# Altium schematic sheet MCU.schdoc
size 282 x 191 mm
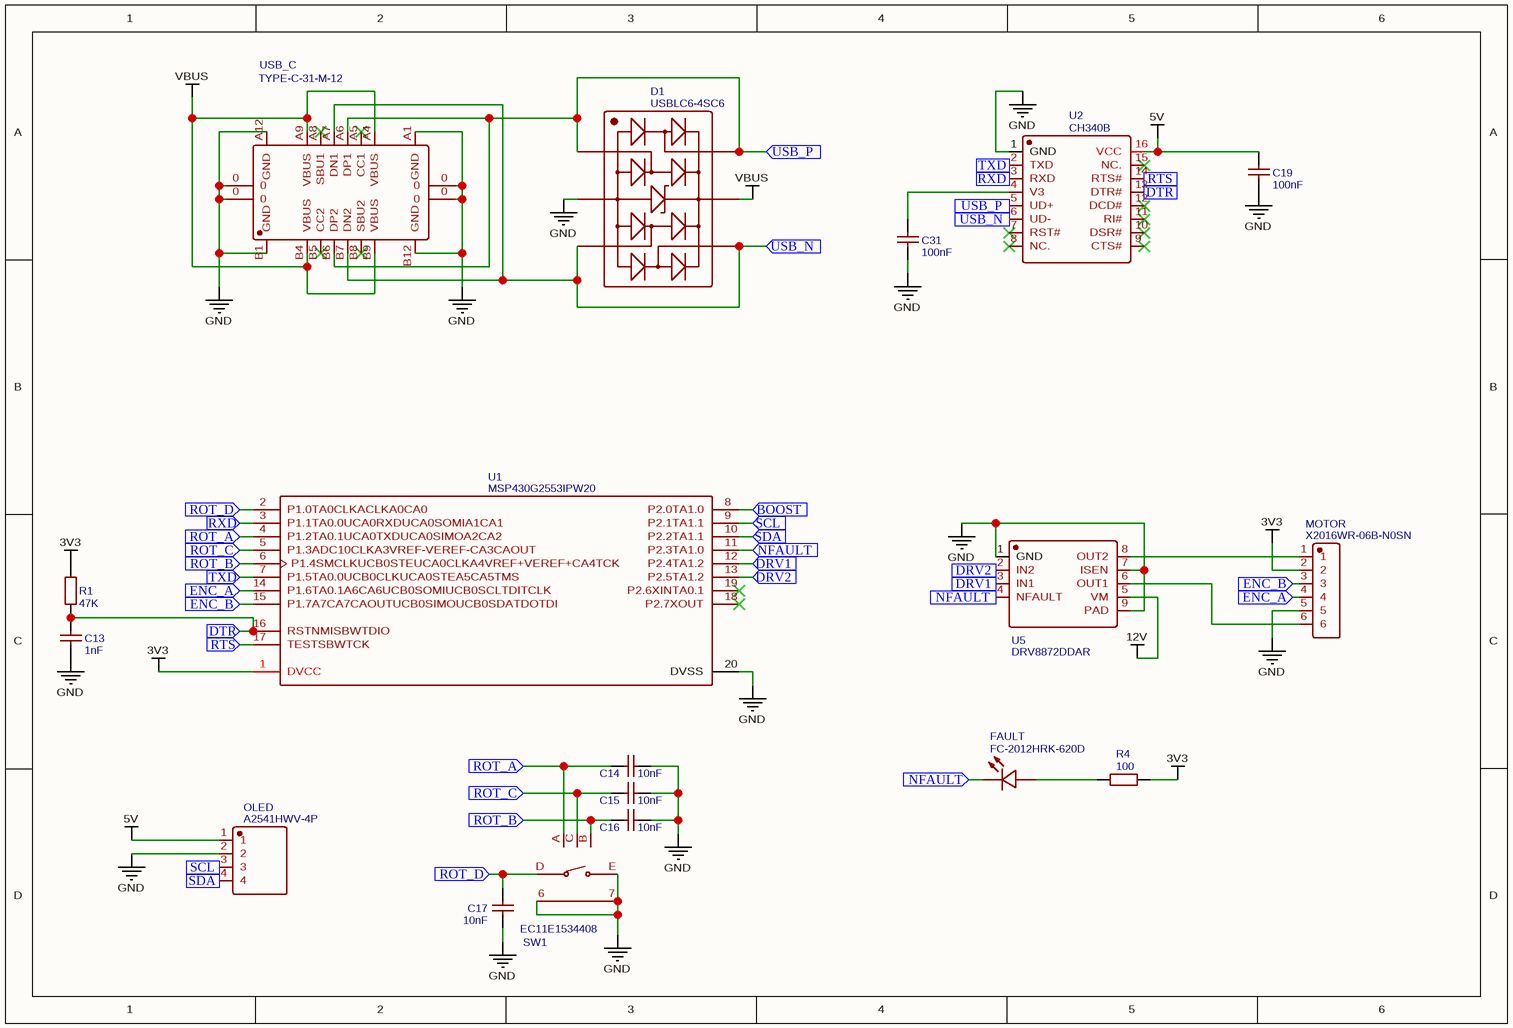
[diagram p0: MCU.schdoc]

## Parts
C13  1nF  [C0603]
C14  10nF  [C0603]
C15  10nF  [C0603]
C16  10nF  [C0603]
C17  10nF  [C0603]
C19  100nF  [C0805]
C31  100nF  [C0805]
D1  USBLC6-4SC6  [SOT-23-6_L2.9-W1.6-P0.95-LS2.8-BR]
FAULT  FC-2012HRK-620D  [LED0805-RD]
MOTOR  X2016WR-06B-N0SN  [CONN-TH_6P-P2.00_X2016WR-06B-N0SN]
OLED  A2541HWV-4P  [OLED12864]
R1  47K  [R0603]
R4  100  [R0603]
SW1  EC11E1534408  [SW-TH_EC11XXXXXXXX]
U1  MSP430G2553IPW20  [TSSOP-20_L6.5-W4.4-P0.65-LS6.4-BL]
U2  CH340B  [SOIC-16_L9.9-W3.9-P1.27-LS6.0-BL]
U5  DRV8872DDAR  [HSOP-8_L5.0-W4.0-P1.27-LS6.2-BL-EP]
USB_C  TYPE-C-31-M-12  [USB-C_SMD-TYPE-C-31-M-12]

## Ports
BOOST (in), DRV1 (in), DRV2 (in), DTR (in), ENC_A (in), ENC_B (in), NFAULT (in), ROT_A (in), ROT_B (in), ROT_C (in), ROT_D (in), RTS (in), RXD (in), SCL (in), SDA (in), TXD (in), USB_N (in), USB_P (in)

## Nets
3V3: MOTOR.2 R1.2 R4.2 U1.1(DVCC)
5V: C19.1 OLED.1 U2.16(VCC)
12V: U5.5(VM)
GND: C13.1 C14.2 C15.2 C16.2 C17.2 C19.2 C31.2 D1.2 MOTOR.5 OLED.2 SW1.6 SW1.7 SW1.E U1.20(DVSS) U2.1(GND) U5.1(GND) U5.7(ISEN) U5.9(PAD) USB_C.0 USB_C.A1(GND) USB_C.A12(GND) USB_C.B1(GND) USB_C.B12(GND)
VBUS: D1.5 USB_C.A4(VBUS) USB_C.A9(VBUS) USB_C.B4(VBUS) USB_C.B9(VBUS)
BOOST: U1.8(P2.0TA1.0) ; port BOOST
DRV1: U1.12(P2.4TA1.2) U5.3(IN1) ; port DRV1
DRV2: U1.13(P2.5TA1.2) U5.2(IN2) ; port DRV2
DTR: C13.2 R1.1 U1.16(RSTNMISBWTDIO) U2.13(DTR#) ; port DTR
ENC_A: MOTOR.4 U1.14(P1.6TA0.1A6CA6UCB0SOMIUCB0SCLTDITCLK) ; port ENC_A
ENC_B: MOTOR.3 U1.15(P1.7A7CA7CAOUTUCB0SIMOUCB0SDATDOTDI) ; port ENC_B
NFAULT: FAULT.1(-) U1.11(P2.3TA1.0) U5.4(NFAULT) ; port NFAULT
ROT_A: C14.1 SW1.A U1.4(P1.2TA0.1UCA0TXDUCA0SIMOA2CA2) ; port ROT_A
ROT_B: C16.1 SW1.B U1.6(P1.4SMCLKUCB0STEUCA0CLKA4VREF+VEREF+CA4TCK) ; port ROT_B
ROT_C: C15.1 SW1.C U1.5(P1.3ADC10CLKA3VREF-VEREF-CA3CAOUT) ; port ROT_C
ROT_D: C17.1 SW1.D U1.2(P1.0TA0CLKACLKA0CA0) ; port ROT_D
RTS: U1.17(TESTSBWTCK) U2.14(RTS#) ; port RTS
RXD: U1.3(P1.1TA0.0UCA0RXDUCA0SOMIA1CA1) U2.3(RXD) ; port RXD
SCL: OLED.3 U1.9(P2.1TA1.1) ; port SCL
SDA: OLED.4 U1.10(P2.2TA1.1) ; port SDA
TXD: U1.7(P1.5TA0.0UCB0CLKUCA0STEA5CA5TMS) U2.2(TXD) ; port TXD
USB_N: D1.3 D1.4 U2.6(UD-) USB_C.A7(DN1) USB_C.B7(DN2) ; port USB_N
USB_P: D1.1 D1.6 U2.5(UD+) USB_C.A6(DP1) USB_C.B6(DP2) ; port USB_P
NetC31_1: C31.1 U2.4(V3)
NetFAULT_2: FAULT.2(+) R4.1
NetMOTOR_1: MOTOR.1 U5.8(OUT2)
NetMOTOR_6: MOTOR.6 U5.6(OUT1)

Not connected (* = marked no-connect by the designer): U1 18(P2.7XOUT)* 19(P2.6XINTA0.1)*; U2 7(RST#)* 8(NC.)* 9(CTS#)* 10(DSR#)* 11(RI#)* 12(DCD#)* 15(NC.)*; USB_C A5(CC1)* A8(SBU1)* B5(CC2)* B8(SBU2)*

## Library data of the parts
C13 = 1nF: BOM_Manufacturer Part: CL10B102KB8NNNC; BOM_Manufacturer: SAMSUNG; nameAlias: Capacitance
C14-C17 = 10nF: BOM_Manufacturer: FH; BOM_Manufacturer Part: 0603B103K500NT; nameAlias: Capacitance
C19 C31 = 100nF: BOM_Manufacturer Part: CC0805KRX7R9BB104; BOM_Manufacturer: YAGEO; nameAlias: Capacitance
D1 = USBLC6-4SC6: BOM_Manufacturer: STMicroelectronics
FAULT = FC-2012HRK-620D: BOM_Manufacturer: NATIONSTAR
MOTOR = X2016WR-06B-N0SN: BOM_Manufacturer: XKB Enterprise; Contributor: LCSC
OLED = A2541HWV-4P: BOM_Manufacturer: Changjiang Connectors; Contributor: LCSC
R1 = 47K: BOM_Manufacturer: UniOhm; BOM_Manufacturer Part: 0603WAF4702T5E; nameAlias: Resistance (Ohms)
R4 = 100: BOM_Manufacturer: UniOhm; BOM_Manufacturer Part: 0603WAF1000T5E; nameAlias: Resistance (Ohms)
SW1 = EC11E1534408: BOM_Manufacturer: ALPS Electric; Contributor: LCSC
U1 = MSP430G2553IPW20: BOM_Manufacturer: TI
U2 = CH340B: BOM_Manufacturer: WCH
U5 = DRV8872DDAR: BOM_Manufacturer: TI
USB_C = TYPE-C-31-M-12: BOM_Manufacturer: Rectangular Connectors - Contacts; Contributor: LCSC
